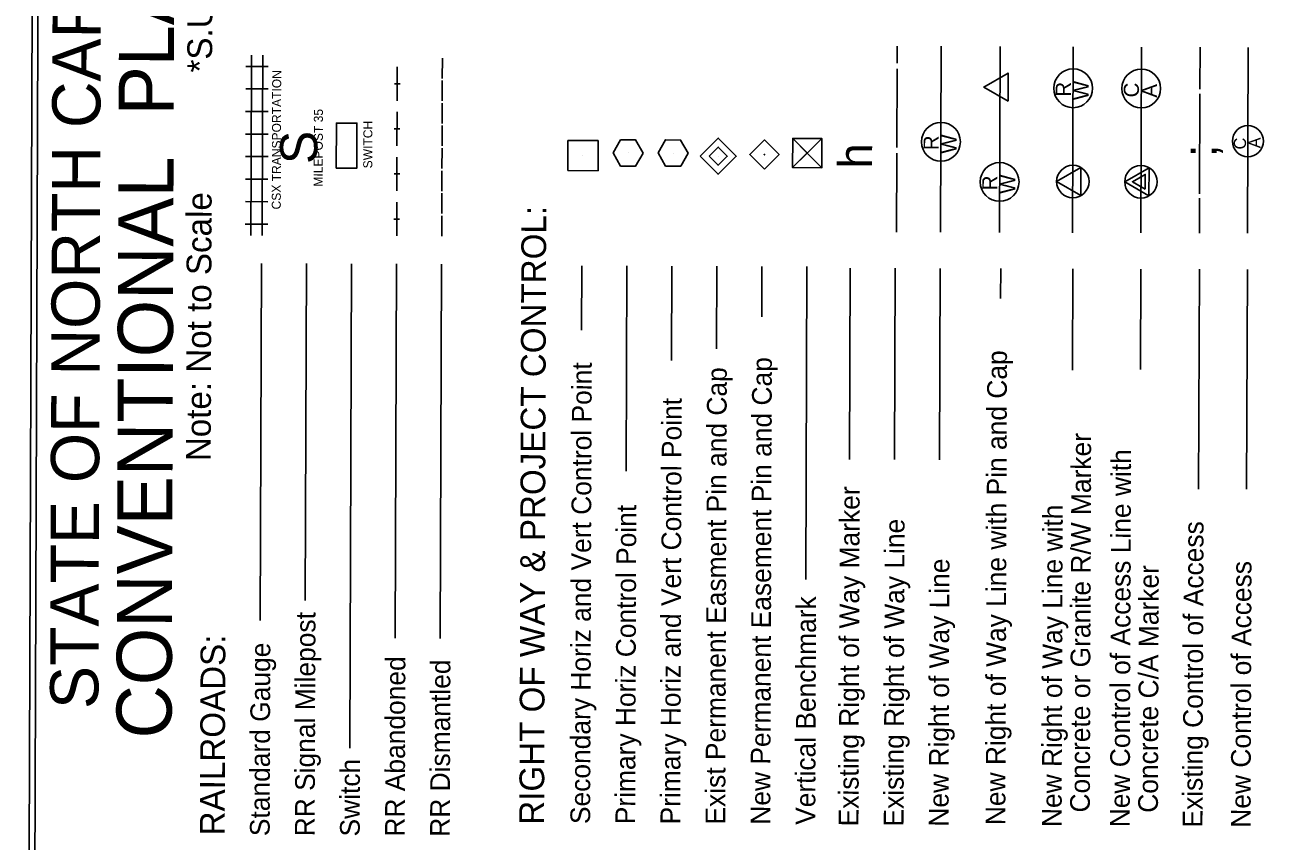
# Model space of a CAD drawing. Extents: x 2364794 to 2387902, y 795230 to 810426.
# Drawn here: x 2372651 to 2376507, y 802522 to 805058 of the extents above; entities that cross this region are included whole.
import ezdxf

# ---------------------------------------------------------------- set-up
doc = ezdxf.new("R2010")
doc.units = 0
for name, color, linetype in [('Default', 7, 'Continuous'), ('Old_Level_22', 7, 'Continuous'), ('Old_Level_5', 7, 'Continuous'), ('Old_Level_62', 7, 'Continuous'), ('Old_Level_63', 7, 'Continuous')]:
    doc.layers.add(name, color=color, linetype=linetype)

# ---------------------------------------------------------------- blocks, each defined once
blk = doc.blocks.new('PRRM')
at = {"layer": 'Old_Level_63'}
blk.add_line((0, 0), (0, 0), dxfattribs=at)
blk.add_lwpolyline([(-0.125, -0.072), (0, 0.144), (0.125, -0.072)], close=True, dxfattribs=at)
blk = doc.blocks.new('RWCON')
at = {"layer": 'Old_Level_63'}
blk.add_line((0, 0), (0, 0), dxfattribs=at)
blk.add_lwpolyline([(-0.125, -0.072), (0, 0.144), (0.125, -0.072)], close=True, dxfattribs=at)
blk.add_circle((0, 0), 0.144, dxfattribs=at)
blk = doc.blocks.new('ROW Marker Permanent Easement-E')
at = {"layer": 'Old_Level_62'}
blk.add_line((0, 0), (0, 0), dxfattribs=at)
for points in [[(0, 0.072), (0.072, 0), (0, -0.072), (-0.072, 0)], [(0, 0.036), (0.036, 0), (0, -0.036), (-0.036, 0)]]:
    blk.add_lwpolyline(points, close=True, dxfattribs=at)
blk = doc.blocks.new('CTL SECONDARY HORIZONTAL AND VERTICAL')
at = {"layer": 'Default'}
blk.add_line((0, 0), (0, 0), dxfattribs=at)
blk.add_lwpolyline([(-0.0735, 0.074), (0.07475, 0.074), (0.07475, -0.0745), (-0.0735, -0.0745)], close=True, dxfattribs=at)
blk = doc.blocks.new('CTL PRIMARY HORIZONTAL')
at = {"layer": 'Default'}
blk.add_line((0, 0), (0, 0), dxfattribs=at)
blk.add_lwpolyline([(0, -0.07375), (-0.06425, -0.03725), (-0.06425, 0.0365), (0, 0.07375), (0.06425, 0.03725), (0.06425, -0.03725), (0, -0.07375)], dxfattribs=at)
blk = doc.blocks.new('CTL PRIMARY HORIZONTAL AND VERTICAL')
at = {"layer": 'Default'}
blk.add_line((0, 0), (0, 0), dxfattribs=at)
blk.add_lwpolyline([(-0.0646, 0.0374), (0.0004, 0.0737), (0.0654, 0.0379), (0.0644, -0.0366), (-0.0006, -0.0743), (-0.0646, -0.0381)], close=True, dxfattribs=at)
blk = doc.blocks.new('EXIST RIGHT OF WAY EASEMENT MARKER')
at = {"layer": 'Default'}
blk.add_line((0, 0), (0, 0), dxfattribs=at)
blk.add_lwpolyline([(-0.072, 0), (0, 0.072), (0.072, 0), (0, -0.072)], close=True, dxfattribs=at)
blk.add_circle((0, 0), 0.0014, dxfattribs=at)
blk = doc.blocks.new('CTL VERTICAL BENCHMARK')
at = {"layer": 'Default'}
blk.add_line((0, 0), (0, 0), dxfattribs=at)
blk.add_lwpolyline([(-0.072, 0.07175), (0.07175, 0.07175), (0.07175, -0.072), (-0.072, -0.072)], close=True, dxfattribs=at)
for points in [[(0.07175, 0.07175), (-0.072, -0.072), (-0.000125, -0.000125), (0.07175, -0.072), (-0.072, 0.07175)], [(-0.000125, -0.000125), (0.07175, 0.07175), (-0.072, 0.07175), (-0.000125, -0.000125)], [(-0.000125, -0.000125), (-0.072, -0.072), (0.07175, -0.072), (-0.000125, -0.000125)]]:
    blk.add_lwpolyline(points, dxfattribs=at)

msp = doc.modelspace()

# ---------------------------------------------------------------- linework, layer by layer
at = {"layer": 'Old_Level_22'}
msp.add_lwpolyline([(2380036.5, 798675.5), (2380077.7, 810340.9), (2372692.1, 810367), (2372650.9, 798701.5)], close=True, dxfattribs=at)
at = {"layer": 'Old_Level_63'}
for p, q in [((2375363.3, 804939.5), (2375363.4, 804992)), ((2375498.2, 804414), (2375500.3, 804991.5)), ((2375681.1, 804413.4), (2375683.2, 804990.9)), ((2375908.6, 804412.6), (2375910.7, 804990)), ((2376120.3, 804411.8), (2376122.4, 804989.3)), ((2376304.5, 804858.3), (2376304.9, 804988.7)), ((2376452.4, 804410.6), (2376454.4, 804988.1)), ((2373355.4, 804894.1), (2373355.7, 804964.1)), ((2373390.4, 804894), (2373390.7, 804964)), ((2373948.7, 804892), (2373949, 804955)), ((2373408, 804928.9), (2373338, 804929.1)), ((2373808.5, 804822.5), (2373808.9, 804927.5)), ((2375362.3, 804677), (2375363.2, 804922)), ((2373355.2, 804824.1), (2373355.4, 804894.1)), ((2373390.2, 804824), (2373390.4, 804894)), ((2373799.9, 804875), (2373817.4, 804874.9)), ((2373948.5, 804822), (2373948.7, 804885)), ((2373407.8, 804858.9), (2373337.8, 804859.1)), ((2373354.9, 804754.1), (2373355.2, 804824.1)), ((2373389.9, 804754), (2373390.2, 804824)), ((2376303.3, 804533.4), (2376304.4, 804844.3)), ((2373407.5, 804788.9), (2373337.5, 804789.1)), ((2373808, 804682.5), (2373808.4, 804787.5)), ((2373948.2, 804752), (2373948.5, 804815)), ((2373354.7, 804684.1), (2373354.9, 804754.1)), ((2373389.7, 804684), (2373389.9, 804754)), ((2373407.3, 804718.9), (2373337.3, 804719.1)), ((2373799.4, 804735), (2373816.9, 804734.9)), ((2373948, 804682), (2373948.2, 804745)), ((2373354.4, 804614.1), (2373354.7, 804684.1)), ((2373389.4, 804614), (2373389.7, 804684)), ((2373947.8, 804612), (2373948, 804675)), ((2373407, 804648.9), (2373337, 804649.1)), ((2373807.5, 804542.5), (2373807.9, 804647.5)), ((2375361.4, 804414.5), (2375362.3, 804659.5)), ((2373354.2, 804544.1), (2373354.4, 804614.1)), ((2373389.2, 804544), (2373389.4, 804614)), ((2373798.9, 804595), (2373816.4, 804594.9)), ((2373947.5, 804542), (2373947.7, 804605)), ((2373406.8, 804578.9), (2373336.8, 804579.1)), ((2376120.9, 804570.7), (2376120.9, 804570.7)), ((2373353.9, 804474.1), (2373354.2, 804544.1)), ((2373388.9, 804474), (2373389.2, 804544)), ((2373947.3, 804472), (2373947.5, 804535)), ((2376302.9, 804411.2), (2376303.3, 804519.4)), ((2373406.5, 804508.9), (2373336.5, 804509.1)), ((2373807, 804402.5), (2373807.4, 804507.5)), ((2373406.3, 804438.9), (2373336.3, 804439.1)), ((2373353.7, 804404.1), (2373353.9, 804474.1)), ((2373388.7, 804404), (2373388.9, 804474)), ((2373798.4, 804455), (2373815.9, 804454.9)), ((2373947, 804402), (2373947.2, 804465)), ((2373386.7, 804317.2), (2373382.8, 803208.3)), ((2373526.7, 804316.7), (2373523, 803269.9)), ((2373666.7, 804316.2), (2373661.4, 802811.8)), ((2373806.7, 804315.7), (2373802.6, 803152.6)), ((2373946.7, 804315.2), (2373942.6, 803152.1)), ((2373946.7, 804315.2), (2373942.6, 803152.1)), ((2374382.7, 804309.9), (2374382, 804110)), ((2374522.7, 804309.4), (2374520.4, 803672.2)), ((2374662.7, 804308.9), (2374661.6, 804015.4)), ((2374802.7, 804308.4), (2374801.8, 804051.5)), ((2374942.7, 804307.9), (2374942.1, 804151.4)), ((2375082.7, 804307.4), (2375079.2, 803335.5)), ((2375217, 804302.8), (2375214.9, 803708.2)), ((2375357, 804302.3), (2375354.9, 803707.7)), ((2375497, 804301.8), (2375494.9, 803707.2)), ((2375684.9, 804301.1), (2375684.6, 804208.4)), ((2375909.2, 804300.3), (2375908.1, 803985.4)), ((2376120.9, 804299.6), (2376119.8, 803987.3)), ((2376302.5, 804298.9), (2376300.1, 803616.1)), ((2376452, 804298.4), (2376449.5, 803615.6))]:
    msp.add_line(p, q, dxfattribs=at)
for points in [[(2372709.6, 810279.4), (2372672.5, 799779.5), (2380015.4, 799753.5), (2380052.5, 810253.5)], [(2373619, 804613.1), (2373619.5, 804753.1), (2373683.2, 804752.9), (2373682.7, 804612.9)], [(2376145.9, 804526.9), (2376146.2, 804614.4), (2376070.5, 804570.9)], [(2376134, 804547.8), (2376094.5, 804570.8), (2376134.2, 804593.5)]]:
    msp.add_lwpolyline(points, close=True, dxfattribs=at)
for centre, radius in [((2375910.2, 804861.2), 60.3), ((2376121.9, 804860.5), 60.3), ((2375499.2, 804694.8), 60.3), ((2376453.4, 804696.8), 48.2), ((2375681.7, 804570.3), 60.3), ((2376120.9, 804570.7), 50.4)]:
    msp.add_circle(centre, radius, dxfattribs=at)

# ---------------------------------------------------------------- block references
at = {"layer": 'Old_Level_5'}
for name, p, xscale, yscale, rotation in [('PRRM', (2375682.7, 804864.5), 350, 349.9999999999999, 89.79761986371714), ('CTL SECONDARY HORIZONTAL AND VERTICAL', (2374386.2, 804651.5), 631.544837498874, 631.544837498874, 89.79761986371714), ('CTL PRIMARY HORIZONTAL', (2374526.3, 804660.2), 631.544837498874, 631.544837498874, 89.79761986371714), ('CTL PRIMARY HORIZONTAL AND VERTICAL', (2374666.3, 804659.7), 631.544837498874, 631.544837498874, 89.79761986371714), ('ROW Marker Permanent Easement-E', (2374806.5, 804650.3), 782.864128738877, 782.8641287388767, 89.79761986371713), ('EXIST RIGHT OF WAY EASEMENT MARKER', (2374950.4, 804655.1), 631.544837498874, 631.544837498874, 89.79761986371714), ('CTL VERTICAL BENCHMARK', (2375083.6, 804659.9), 631.544837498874, 631.544837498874, 89.79761986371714), ('RWCON', (2375909.2, 804571.4), 350, 349.9999999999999, 89.79761986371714)]:
    msp.add_blockref(name, p, dxfattribs=dict(at, xscale=xscale, yscale=yscale, rotation=rotation))

# ---------------------------------------------------------------- texts
at = {"layer": 'Old_Level_63'}
for s, height, p in [('STATE OF NORTH CAROLINA, DIVISION OF HIGHWAYS', 149.933, (2372879.4, 802932.7)), ('CONVENTIONAL  PLAN SHEET SYMBOLS', 171.362, (2373107.1, 802841.2)), ('*S.U.E. = Subsurface Utility Engineering', 77, (2373233.1, 804910)), ('CSX TRANSPORTATION', 28, (2373446.6, 804484.7)), ('R', 47.2, (2375903, 804835.3)), ('W', 47.2, (2375958.6, 804824.3)), ('C', 47.2, (2376114.7, 804832.8)), ('A', 47.2, (2376170.4, 804832.1)), ('MILEPOST 35', 28, (2373576.9, 804555.5)), ('SWITCH', 28, (2373731.1, 804612.4)), ('S', 115.5, (2373560.2, 804625.7)), ('R', 47.2, (2375492.1, 804668.9)), ('W', 47.2, (2375547.7, 804658)), ('A', 37.8, (2376493, 804674.7)), ('h', 105, (2375285.1, 804612)), (';', 105, (2376356.2, 804647.2)), ('C', 37.8, (2376447.6, 804671.1)), ('W', 47.2, (2375730.1, 804533.4)), ('R', 47.2, (2375674.5, 804544.4)), ('Note: Not to Scale', 77, (2373228.8, 803702.7)), ('RIGHT OF WAY & PROJECT CONTROL:', 77, (2374265.3, 802573.4)), ('New Permanent Easement Pin and Cap', 61.25, (2374968.4, 802573.5)), ('New Right of Way Line with Pin and Cap', 61.25, (2375699.3, 802572.1)), ('Secondary Horiz and Vert Control Point', 61.25, (2374408.4, 802575.5)), ('Exist Permanent Easment Pin and Cap', 61.25, (2374828.4, 802574)), ('Primary Horiz and Vert Control Point', 61.25, (2374688.4, 802574.5)), ('  Concrete or Granite R/W Marker', 61.25, (2375961.8, 802565.9)), ('New Control of Access Line with', 61.25, (2376086, 802565.5)), ('Existing Right of Way Marker', 61.25, (2375242.7, 802568.4)), ('Primary Horiz Control Point', 61.25, (2374548.4, 802575)), ('New Right of Way Line with', 61.25, (2375874.3, 802566.2)), ('Existing Right of Way Line', 61.25, (2375382.7, 802567.9)), ('Existing Control of Access', 61.25, (2376312.2, 802564.7)), ('New Right of Way Line', 61.25, (2375522.7, 802567.4)), ('  Concrete C/A Marker', 61.25, (2376173.5, 802565.1)), ('New Control of Access', 61.25, (2376461.7, 802564.1)), ('Vertical Benchmark', 61.25, (2375108.4, 802573)), ('RR Signal Milepost', 61.25, (2373552.1, 802537.5)), ('RAILROADS:', 77, (2373272.3, 802540.4)), ('Standard Gauge', 61.25, (2373412.1, 802538)), ('RR Abandoned', 61.25, (2373832.1, 802536.5)), ('RR Dismantled', 61.25, (2373972.1, 802536)), ('Switch', 61.25, (2373692.1, 802537))]:
    msp.add_text(s, height=height, rotation=89.7976, dxfattribs=at).set_placement(p)

doc.saveas('drawing.dxf')
